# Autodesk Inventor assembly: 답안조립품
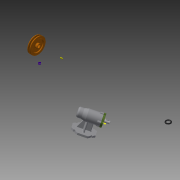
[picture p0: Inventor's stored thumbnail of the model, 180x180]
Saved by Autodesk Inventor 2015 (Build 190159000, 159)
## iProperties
Created: 2019-12
Part Number: 답안조립품
Document SubType Name: Assembly
Designer: now
Author: now
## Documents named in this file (12)
- C:\Users\now\Desktop\12221김찬희\491204V1073\답안조립품.iam
- C:\Users\now\Desktop\12221김찬희\491204V1073\Ű 5 x 5 x 16.ipt
- C:\Users\now\Desktop\12221김찬희\491204V1073\V벨트풀리.ipt
- C:\Users\now\Desktop\12221김찬희\491204V1073\멈춤나사 M3.ipt
- C:\Users\now\Desktop\12221김찬희\491204V1073\베어링 6004.ipt
- C:\Users\now\Desktop\12221김찬희\491204V1073\베어링 51202.ipt
- C:\Users\now\Desktop\12221김찬희\491204V1073\볼트 M4.ipt
- C:\Users\now\Desktop\12221김찬희\491204V1073\부품1.ipt
- C:\Users\now\Desktop\12221김찬희\491204V1073\어댑터슬리브.ipt
- C:\Users\now\Desktop\12221김찬희\491204V1073\오일 실.ipt
- C:\Users\now\Desktop\12221김찬희\491204V1073\축.ipt
- C:\Users\now\Desktop\12221김찬희\491204V1073\커버.ipt
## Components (2 placed, 2 different names)
1. Ű 5 x 5 x 16:1
2. V벨트풀리:1
